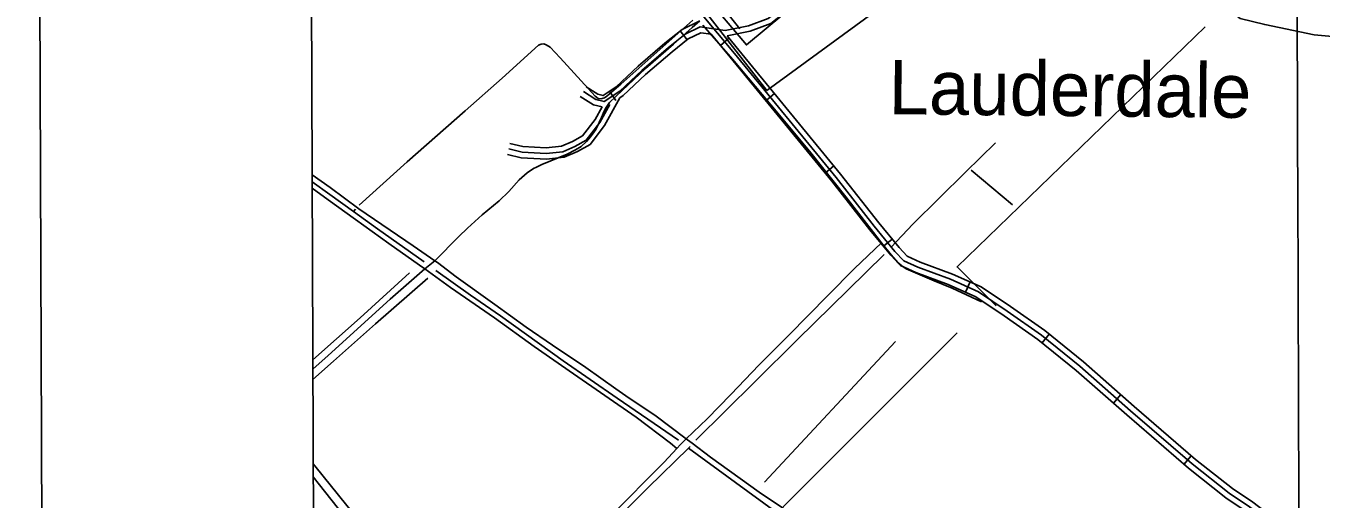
# Model space of a CAD drawing. Extents: x 3405885 to 3443815, y 558517 to 583997.
# Drawn here: x 3409221 to 3412686, y 571978 to 573242 of the extents above; entities that cross this region are included whole.
import ezdxf

# ---------------------------------------------------------------- set-up
doc = ezdxf.new("R2010")
doc.units = 0
for name, color, linetype in [('V-ANNO-SYMB', 7, 'Continuous'), ('V-DTCH-CNTR', 7, 'Continuous'), ('V-GRID-FRAM', 7, 'Continuous'), ('V-GRID-MAJR', 7, 'Continuous'), ('V-ROAD-CNTR', 7, 'Continuous'), ('V-SITE-OTLN', 7, 'Continuous'), ('V-TOPO-GNAM-IDEN', 7, 'Continuous'), ('V-TOPO-SHOR', 7, 'Continuous')]:
    doc.layers.add(name, color=color, linetype=linetype)

msp = doc.modelspace()

# ---------------------------------------------------------------- linework, layer by layer
at = {"layer": 'V-ANNO-SYMB'}
msp.add_lwpolyline([(3409312.5, 559736.2), (3442395.5, 559868.5), (3442303.8, 582784.9), (3409220.9, 582652.6), (3409312.5, 559736.2)], dxfattribs=at)
at = {"layer": 'V-DTCH-CNTR'}
for points in [[(3409988.8, 572325), (3410029.8, 572361.9), (3410195.8, 572512), (3410288.1, 572593.2), (3410315.3, 572614.8), (3410379.4, 572679.5), (3410402.1, 572702.2), (3410441.3, 572738), (3410487.1, 572775.3), (3410513.2, 572800.1), (3410540.8, 572831), (3410562, 572849.5), (3410579.3, 572861.7), (3410586.6, 572865.3), (3410601.3, 572872.4), (3410668.9, 572899.9), (3410691.7, 572911.4), (3410706.3, 572920.1), (3410721, 572933.6), (3410731.5, 572945.7), (3410739.7, 572956.4), (3410745.3, 572965.3), (3410755, 572984), (3410761.3, 572997.8), (3410767.8, 573015), (3410773.4, 573024.4), (3410782.6, 573038), (3410816, 573069.9), (3410878.8, 573128.6), (3410953.3, 573193.4), (3411003.8, 573238), (3411024.2, 573256.4)], [(3411032.4, 573244.8), (3411111.8, 573153.4), (3411232.6, 573009.2), (3411321, 572903.2), (3411414.9, 572785.3), (3411510.3, 572662.4), (3411535.7, 572631), (3411553.7, 572610.7), (3411564.2, 572601.2), (3411576.3, 572593.6), (3411651.1, 572561.6), (3411698.8, 572542), (3411750.4, 572517.5), (3411777.6, 572504.7)], [(3411258.7, 571945.4), (3411182.5, 571996.9), (3411052.3, 572090.3), (3411003.9, 572127.4), (3410991.1, 572136.3), (3410987.2, 572139.2), (3410903.4, 572201.9), (3410835.3, 572247.8), (3410799.6, 572272.3), (3410718.9, 572329.4), (3410629.4, 572389.1), (3410559.5, 572437.8), (3410475.1, 572497.8), (3410372, 572572.3), (3410322.4, 572609.9), (3410315.3, 572614.8), (3410257.4, 572654.7), (3410111.3, 572753.9), (3410034.5, 572810.6), (3409986.9, 572844.1)], [(3409987.1, 572808.6), (3410029.2, 572777.7), (3410102.3, 572725.3), (3410191.8, 572660.8), (3410274, 572603.4), (3410288.1, 572593.2), (3410357.1, 572543.1), (3410474.8, 572462.3), (3410581, 572385.5), (3410685.7, 572312.8), (3410853.2, 572196.7), (3410945.4, 572127.5), (3410962.4, 572112.9)], [(3410972.6, 572123.9), (3410987.2, 572139.2), (3411043.6, 572192.4), (3411107.2, 572257.6), (3411183, 572336.4), (3411262.4, 572416.2), (3411366.5, 572522.3), (3411437.7, 572594), (3411510.3, 572662.4)], [(3410972.6, 572123.9), (3410962.4, 572112.9), (3410928.7, 572076.7), (3410782.8, 571930.4), (3410695.3, 571844.9), (3410579.2, 571730.5), (3410476.4, 571628.6), (3410399.6, 571553.3), (3410330.5, 571632.3), (3410297.4, 571676.7), (3410215.1, 571785.5), (3410169.3, 571849.5), (3410158.2, 571864.4), (3410079.2, 571960.5), (3409993.6, 572066.8), (3409989.7, 572071.9)]]:
    msp.add_lwpolyline(points, dxfattribs=at)
at = {"layer": 'V-GRID-FRAM'}
msp.add_lwpolyline([(3409954, 582088.9), (3441575.2, 582215.4), (3441655.9, 564032.2), (3410018.8, 563905.7), (3409954, 582088.9)], dxfattribs=at)
at = {"layer": 'V-GRID-MAJR'}
msp.add_spline([(3412655.2, 563916.2), (3412633.2, 569976.2), (3412611.1, 576037.3), (3412589.1, 582098.4), (3412589.1, 582099.4)], degree=3, dxfattribs=at)
at = {"layer": 'V-ROAD-CNTR'}
for p, q in [((3410989.9, 573205.6), (3410971.2, 573229)), ((3411101.9, 573209.6), (3411078.9, 573190.4)), ((3410798.8, 573042.8), (3410782.3, 573067.9)), ((3411223.9, 573061.6), (3411200.7, 573042.5)), ((3411382.6, 572868.4), (3411359.4, 572849.3)), ((3411538.4, 572672.8), (3411515.2, 572653.8)), ((3411747.3, 572558.5), (3411735.1, 572531.1)), ((3411958.6, 572418.7), (3411939.7, 572395.4)), ((3412150.1, 572257.3), (3412130.4, 572234.6)), ((3412338.9, 572093.5), (3412319.3, 572070.8))]:
    msp.add_line(p, q, dxfattribs=at)
for points in [[(3411393.1, 573929.4), (3411195.7, 573779.2), (3410949, 573589.2), (3410910.6, 573544.3), (3410912.1, 573515.6), (3410973.2, 573441.4), (3411085.3, 573291.8), (3411131.4, 573234.8)], [(3410712.3, 573067), (3410745.4, 573045.9), (3410767.6, 573040.2), (3410809.9, 573068.1), (3410868.9, 573123.7), (3410940.3, 573185.1), (3410984.5, 573220.5), (3411024.5, 573239.9), (3411091.4, 573230.1), (3411154.3, 573242.6), (3411206.8, 573262.1), (3411255.8, 573300.8), (3411380.7, 573396.4), (3411489.4, 573480.6), (3411609.1, 573574.1), (3411652.4, 573605.7)], [(3411661.2, 573593.6), (3411618.1, 573562.2), (3411498.6, 573468.7), (3411389.9, 573384.6), (3411265, 573289), (3411214.2, 573248.9), (3411158.4, 573228.1), (3411096.8, 573215.8)], [(3410894.1, 573436.3), (3411116.8, 573168.4), (3411388.8, 572837.2), (3411490.8, 572707.2), (3411546, 572639.9), (3411570, 572615), (3411607.6, 572597.5), (3411694.5, 572565.5), (3411769.6, 572532.1), (3411846.4, 572480), (3411937.7, 572416.5), (3412040.6, 572332.9), (3412176.6, 572214.2), (3412340.8, 572072), (3412440.1, 571993.8), (3412494.5, 571957.2), (3412546.6, 571918.1), (3412645.9, 571817.7), (3412791.4, 571678.4), (3413116.3, 571365), (3413350.3, 571148.4)], [(3411024.1, 573256.4), (3410976.4, 573233.2), (3410930.7, 573196.7), (3410858.8, 573134.9), (3410800.5, 573079.9), (3410764.9, 573056.4), (3410751.4, 573059.9), (3410720.3, 573079.6)], [(3411054, 573220.4), (3411026.9, 573224.4), (3410992.6, 573207.7), (3410949.9, 573173.6), (3410878.9, 573112.6), (3410819.2, 573056.3), (3410809.7, 573050)], [(3411054, 573220.4), (3411105.2, 573158.8), (3411377.1, 572827.8), (3411479.1, 572697.8), (3411534.8, 572629.9), (3411561.2, 572602.6), (3411601.8, 572583.6), (3411688.8, 572551.6), (3411762.3, 572518.9), (3411837.9, 572467.6), (3411928.6, 572404.5), (3412030.9, 572321.4), (3412166.8, 572202.9), (3412331.2, 572060.4), (3412431.3, 571981.7), (3412485.8, 571945), (3412536.7, 571906.8), (3412635.4, 571807), (3412677.6, 571766.7)], [(3411096.8, 573215.8), (3411128.4, 573177.9), (3411400.5, 572846.6), (3411502.5, 572716.6), (3411557.2, 572649.9), (3411578.9, 572627.5), (3411613.4, 572611.4), (3411700.1, 572579.4), (3411776.9, 572545.2), (3411854.9, 572492.3), (3411946.7, 572428.4), (3412050.2, 572344.4), (3412186.5, 572225.6), (3412350.4, 572083.6), (3412448.9, 572005.9), (3412503.2, 571969.5), (3412556.5, 571929.4), (3412656.4, 571828.4), (3412697.8, 571788.8)], [(3410809.7, 573050), (3410769.2, 572976), (3410730.3, 572925.8), (3410696.3, 572906.5), (3410661.1, 572891.7), (3410613.3, 572886.4), (3410546.2, 572890.4), (3410509.2, 572898.9)], [(3410783.1, 573032.7), (3410756.6, 572984.3), (3410720.3, 572937.3), (3410689.7, 572920), (3410657.3, 572906.4), (3410612.9, 572901.4), (3410548.4, 572905.3), (3410512.6, 572913.6)], [(3410762.4, 573026.1), (3410739.3, 573032), (3410704.2, 573054.3)], [(3410762.4, 573026.1), (3410744, 572992.5), (3410710.3, 572948.9), (3410683.1, 572933.5), (3410653.5, 572921), (3410612.5, 572916.5), (3410550.5, 572920.2), (3410515.9, 572928.2)]]:
    msp.add_lwpolyline(points, dxfattribs=at)
at = {"layer": 'V-SITE-OTLN'}
msp.add_lwpolyline([(3411390.5, 573393.4), (3411148.5, 573191.7), (3411035.9, 573326.7)], dxfattribs=at)
at = {"layer": 'V-TOPO-SHOR'}
for p, q in [((3411749.6, 572857.4), (3411860.1, 572764.2)), ((3410103, 572752.4), (3410097.5, 572746.2)), ((3411246.6, 571957.7), (3411712.8, 572422.2)), ((3411196.8, 572023.6), (3411547.7, 572399.5))]:
    msp.add_line(p, q, dxfattribs=at)
for points in [[(3410594.7, 573849.5), (3410960.1, 573382.8), (3411203.6, 573069.9), (3411544, 573319.1)], [(3412198.5, 573514.5), (3412331.3, 573355.3), (3412414.1, 573306.1), (3412469.4, 573262.2), (3412535.5, 573246), (3412667.8, 573219), (3412833.1, 573203.1), (3413009.2, 573225.8), (3413488.1, 573271.8), (3413719.3, 573289.3), (3413818.4, 573306.2), (3413895.2, 573361.5), (3414010.5, 573450.1), (3414131.2, 573566.2)], [(3411005.6, 573258.2), (3410901.3, 573165.6), (3410812.3, 573086.4), (3410775.2, 573055.1), (3410769.1, 573050), (3410759.5, 573048), (3410751.7, 573048.3), (3410744, 573054.4), (3410649.9, 573157.5), (3410623.3, 573185.4), (3410613.2, 573191.9), (3410606.7, 573194.5), (3410599.7, 573194), (3410592.4, 573190.9), (3410495, 573103), (3410396, 573015.6)], [(3411817.2, 572494.2), (3411712.1, 572598.4), (3412375.9, 573239.8)], [(3410396, 573015.6), (3410241.3, 572879.6), (3410112.9, 572763.7)], [(3411814.7, 572930), (3411734.6, 572851.6), (3411593.7, 572712.4), (3411535.7, 572651.6)], [(3410286.2, 572612.4), (3410161.8, 572699.8), (3410097.5, 572746.2), (3410034.3, 572791.8), (3409987, 572825.6)], [(3411517.1, 572631.3), (3411420.5, 572537.3), (3411285.4, 572404.3), (3411171.6, 572292), (3411013.2, 572135.2)], [(3410247.4, 572582.2), (3410115.1, 572462.2), (3409988.7, 572350.2)], [(3410967.2, 572135.2), (3410803.2, 572247.3), (3410658.6, 572347.2), (3410490.3, 572467.6), (3410410.6, 572522.7), (3410317.3, 572589.2)], [(3410295.9, 572568.5), (3410156.2, 572446.5), (3410044.2, 572346.9), (3409988.9, 572297.5)], [(3410998.3, 572118.9), (3410993.3, 572113.9), (3410886.1, 572008.9), (3410738.4, 571861.5), (3410588.4, 571713.7), (3410418.2, 571543.3)], [(3411228.6, 571943.1), (3411119.3, 572022.2), (3410993.3, 572113.9)], [(3409989.8, 572037.2), (3410006.3, 572015.9), (3410121.1, 571870.9)]]:
    msp.add_lwpolyline(points, dxfattribs=at)

# ---------------------------------------------------------------- texts
at = {"layer": 'V-TOPO-GNAM-IDEN'}
msp.add_text('Lauderdale', height=145, rotation=359.3917, dxfattribs=at).set_placement((3411528.7, 573006.8))

doc.saveas('drawing.dxf')
